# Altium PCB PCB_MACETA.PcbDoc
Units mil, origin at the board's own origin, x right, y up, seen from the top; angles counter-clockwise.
Board outline 2644 x 1425 mil, 2 copper layers (Top Layer, Bottom Layer); 33 components, 22 nets, 122 pads, 124 vias.
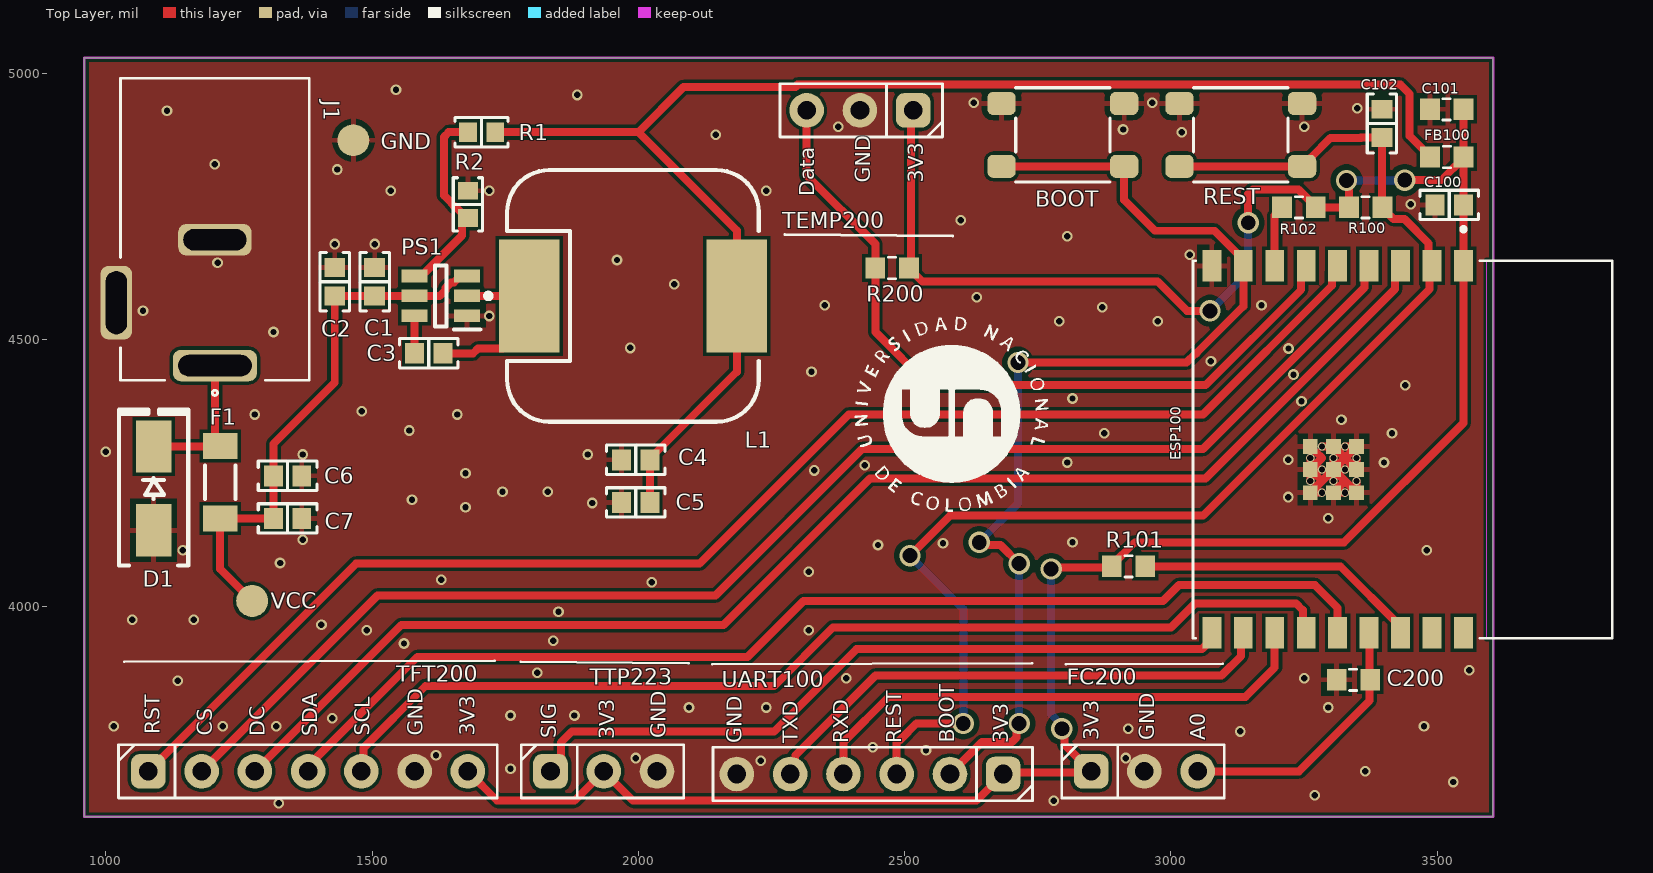
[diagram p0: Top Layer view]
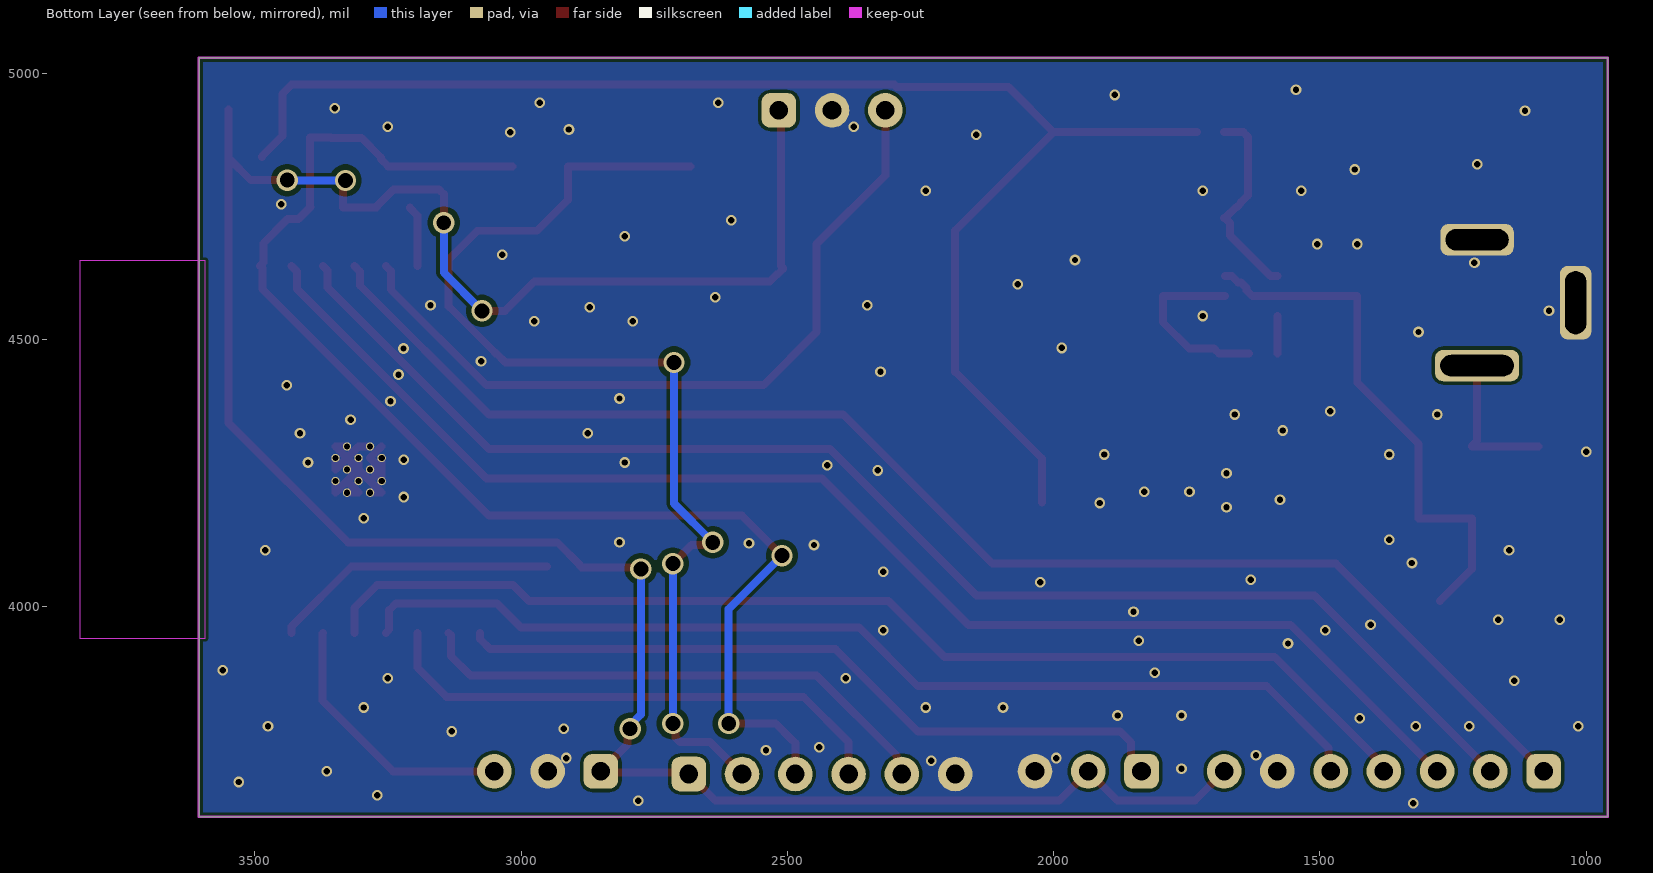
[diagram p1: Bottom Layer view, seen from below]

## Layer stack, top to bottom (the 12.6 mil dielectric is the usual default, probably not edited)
Top Solder: solder mask 0.4, Solder Resist, Dk 3.5
Top Layer: signal copper 1.4
Dielectric 1: dielectric 12.6, FR-4, Dk 4.8
Bottom Layer: signal copper 1.4
Bottom Solder: solder mask 0.4, Solder Resist, Dk 3.5

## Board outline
960,3605 3604,3605 3604,5030 960,5030

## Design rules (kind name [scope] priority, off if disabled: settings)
Clearance Clearance_Vias [IsVia] p1: gap=10 ignorepadtopadclearanceinfootprint=FALSE except(0: Arc-Hole Track-Hole SMDPad-Hole THPad-Hole Via-Hole Fill-Hole Poly-Hole Region-Hole Text-Hole)
Clearance [All] p2: gap=6 ignorepadtopadclearanceinfootprint=FALSE
HoleSize [All] p1: absolutevalues=TRUE maxlimit=200 minlimit=12 maxpercent=80.000 minpercent=20.000
MinimumAnnularRing [All] p1: minimumring=3
MinimumSolderMaskSliver [All] p1: minsoldermaskwidth=4
PolygonConnect PolygonConnect_3 [All vs IsNamedPolygon('GND_Top')] p1: thpad.connectstyle=Direct thpad.reliefconductorwidth=10 thpad.reliefentries=4 thpad.polygonreliefangle="90 Angle" thpad.airgapwidth=10 smdpad.connectstyle=Relief smdpad.reliefconductorwidth=10 smdpad.reliefentries=4 smdpad.polygonreliefangle="90 Angle" smdpad.airgapwidth=10 via.connectstyle=Direct via.reliefconductorwidth=10 via.reliefentries=4 via.polygonreliefangle="90 Angle" via.airgapwidth=10
PolygonConnect PolygonConnect_2 [All vs IsNamedPolygon('GND')] p2: connectstyle=Direct reliefconductorwidth=10 reliefentries=4 polygonreliefangle="90 Angle" airgapwidth=10
PolygonConnect GND [All vs IsNamedPolygon('GND_Top')] p3: thpad.connectstyle=Direct thpad.reliefconductorwidth=10 thpad.reliefentries=4 thpad.polygonreliefangle="90 Angle" thpad.airgapwidth=10 smdpad.connectstyle=Relief smdpad.reliefconductorwidth=10 smdpad.reliefentries=4 smdpad.polygonreliefangle="90 Angle" smdpad.airgapwidth=10 via.connectstyle=Direct via.reliefconductorwidth=10 via.reliefentries=4 via.polygonreliefangle="90 Angle" via.airgapwidth=10
PolygonConnect PolygonConnect_1 [All vs IsNamedPolygon('GND_Top')] p4: thpad.connectstyle=Direct thpad.reliefconductorwidth=10 thpad.reliefentries=4 thpad.polygonreliefangle="90 Angle" thpad.airgapwidth=10 smdpad.connectstyle=Relief smdpad.reliefconductorwidth=10 smdpad.reliefentries=4 smdpad.polygonreliefangle="90 Angle" smdpad.airgapwidth=10 via.connectstyle=Relief via.reliefconductorwidth=10 via.reliefentries=4 via.polygonreliefangle="90 Angle" via.airgapwidth=10
PolygonConnect [All] p5: connectstyle=Direct reliefconductorwidth=8 reliefentries=4 polygonreliefangle="90 Angle" airgapwidth=6
RoomDefinition ESP32 [InComponentClass('ESP32')] p1: confinementstyle=ConfineIn formatcopy=TRUE lockcomponents=FALSE outline 0,0 2000,0 2000,1000 0,1000
RoomDefinition Designator [InComponentClass('Designator')] p2: confinementstyle=ConfineIn formatcopy=TRUE lockcomponents=FALSE outline 0,0 2000,0 2000,1000 0,1000
RoutingVias [All] p1: holewidth=12 width=22 viastyle="Through Hole" minholewidth=12 minwidth=18 maxholewidth=30 maxwidth=40
SilkToSilkClearance [All] p1: silktosilkclearance=2
SilkToSolderMaskClearance [IsPad] p1: minsilkscreentomaskgap=0.1 clearancetoexposedcopper=TRUE
SolderMaskExpansion SolderMaskExpansion_Vias [IsVia] p1: expansion=2 istentingtop=TRUE
SolderMaskExpansion [All] p2: expansion=2 istentingtop=FALSE
Width [All] p1: maxlimit=100 minlimit=6 preferedwidth=10
26 further rules are at their usual default settings.

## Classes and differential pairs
component class POWER: C1 C2 C3 C4 C5 D1 F1 J1 L1 PS1 R1 R2 VCC vcc
component class ESP32: BOOT C100 C101 C102 ESP100 FB100 R100 R101 R102 REST UART100
component class Designator: C200 FC200 R200 TEMP200 TFT200 TTP223

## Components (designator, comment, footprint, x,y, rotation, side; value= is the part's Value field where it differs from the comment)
BOOT "Sw" Sw_PUSH_4.5x4.5x5mm 2797,4885 r180 top (schematic designator SW100)
C1 "4.7 µF" "CAP 0603_1608" 1505,4609.17 r270 top
C2 "0.1 µF" "CAP 0603_1608" 1430,4609.17 r270 top
C3 "0.1 µF" "CAP 0603_1608" 1606.57,4475 r180 top
C4 "22 µF" "CAP 0603_1608" 1995,4275 r0 top
C5 "22 µF" "CAP 0603_1608" 1995,4195 r0 top
C6 "0.1 µF" "CAP 0603_1608" 1341.57,4245 r180 top
C7 "10 µF" "CAP 0603_1608" 1341.57,4165 r180 top
C100 "10 µF" "CAP 0603_1608" 3522.52,4753.39 r0 top
C101 "0.1uF 50V" 0603_cap#1 3517.59,4933 r180 top value=0.1uF
C102 "1 µF" "CAP 0603_1608" 3396,4906.43 r270 top
C200 "0.1uF 50V" 0603_cap#2 3342.5,3862 r180 top value=0.1uF
D1 "SMAJ5.0A" "DO214AC SMA" 1090,4221.26 r90 top
ESP100 "ESP32-C3-WROOM-02-N4" ESP32-C3-WROOM-02-N4 3312.87,4294.49 r270 top
F1 "MFU1206FF05000P100" "FUSE 1206_3216 0.6MM" 1215,4232.91 r270 top
FB100 "60OHM 2A" 0603_fb 3517.59,4843.35 r0 top value="60 OHM"
FC200 "3x1" H_3X1_TH_100mil 2950,3690 r0 top
GND "GND" Pad_SMD 1465,4875 r90 top (schematic designator TP2)
J1 "PWR JACK 2.1mm" CON_POWER_BARREL_2.1MM_3CONN 1205,4570 r180 top
L1 "5.6 µH" "WURTH WE-PD 1280" 1989.88,4582.6 r0 top (schematic designator L?)
PS1 "LMR51430XDDCR" SOT95P280X110-6N 1629.21,4582.6 r180 top
R1 "100 kOhms" "RES 0603_1608" 1705.59,4890 r0 top
R2 "22.1 kOhms" "RES 0603_1608" 1680,4754.41 r270 top
R100 "10k 1/10W" 0603_res 3365.5,4749 r180 top value=10k
R101 "10k 1/10W" 0603_res 2920,4075 r0 top value=10k
R102 "10k 1/10W" 0603_res 3240,4749 r0 top value=10k
R200 "4k7 1/10W" 0603_res 2476.5,4635 r180 top value=4k7
REST "Sw" Sw_PUSH_4.5x4.5x5mm 3131,4885 r180 top (schematic designator SW101)
TEMP200 "3x1" H_3X1_TH_100mil 2416,4931 r180 top
TFT200 "7x1" H_7x1_TH_100mil 1380,3690 r0 top
TTP223 "3x1" H_3X1_TH_100mil 1935,3690 r0 top
UART100 "6x1" H_6x1_TH_100mil 2435,3685 r180 top
VCC "5V" Pad_SMD 1275,4010 r0 top (schematic designator TP1)

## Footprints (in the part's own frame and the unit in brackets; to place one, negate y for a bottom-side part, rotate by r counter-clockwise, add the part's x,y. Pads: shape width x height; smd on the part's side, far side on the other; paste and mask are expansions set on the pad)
0603_cap#1 [mil]
  rect 37x40 smd: 2(-31.5,0) 2(31.5,0)
  silkscreen extent -7,-20 8,20, body extent -31,-17 31,17, height 34
0603_cap#2 [mil]
  rect 37x40 smd: 1(-31.5,0) 2(31.5,0)
  silkscreen extent -7,-20 8,20, body extent -31,-17 31,17, height 34
0603_fb [mil]
  rect 37x40 smd: 1(-31.5,0) 2(31.5,0)
  silkscreen extent -6,-20 8,20, body extent -32,-16 31,16, height 32
0603_res [mil] "1608 Metric / 20190225 / C-A.Serna.A"
  rect 37x40 smd: 1(-31.5,0) 2(31.5,0)
  silkscreen extent -7,-20 8,20, body extent -31,-16 32,16, height 12
"CAP 0603_1608" [mm] "Chip Capacitor, 2-Leads, Body 1.60x0.80mm, IPC Medium Density"
  rect 0.9x1 smd: 1(-0.675,0) 2(0.675,0)
  silkscreen extent -1.4,-0.7 1.4,0.7, body extent -0.8,-0.41 0.8,0.41, height 0.82
CON_POWER_BARREL_2.1MM_3CONN [mm]
  rrect50% 4x1.5 hole 1.016 slot 3.5 at 0 deg: 1(0,3)
  rrect50% 3.5x1.5 hole 1.016 slot 3 at 0 deg: 2(0,-3)
  rrect50% 1.5x3.5 hole 1.016 slot 3 at 90 deg: 3(4.7,0)
  silkscreen extent -4.5,-10.7 4.5,4.42, body extent -4.5,-10.7 4.9,3.7, height 11
"DO214AC SMA" [mm] "Molded Diode, 2-Leads, Body 4.30x2.60mm, IPC Medium Density"
  rect 2.5x1.7 smd: 1(-2,0) 2(2,0)
  silkscreen extent -3.68,-1.65 3.75,1.65, body extent -2.6,-1.37 2.6,1.37, height 2.4
ESP32-C3-WROOM-02-N4 [mm]
  rect 1.5x0.9 smd: 1(-8.75,6) 2(-8.75,4.5) 3(-8.75,3) 4(-8.75,1.5) 5(-8.75,0) 6(-8.75,-1.5) 7(-8.75,-3) 8(-8.75,-4.5) 9(-8.75,-6) 10(8.75,-6) 11(8.75,-4.5) 12(8.75,-3) 13(8.75,-1.5) 14(8.75,0) 15(8.75,1.5) 16(8.75,3) 17(8.75,4.5) 18(8.75,6)
  rect 0.7x0.7 smd: 19(-0.14,0.9) 19(-0.14,-0.2) 19(-0.14,-1.3) 19(0.96,0.9) 19(0.96,-0.2) 19(0.96,-1.3) 19(2.06,-0.2) 19(2.06,0.9) 19(2.06,-1.3)
  round 0.4 hole 0.3 mask+0: 19(-0.14,0.35) 19(-0.14,-0.75) 19(0.41,0.9) 19(0.41,-0.2) 19(0.41,-1.3) 19(0.96,0.35) 19(0.96,-0.75) 19(1.51,0.9) 19(1.51,-0.2) 19(1.51,-1.3) 19(2.06,-0.75) 19(2.06,0.35)
  Keep-Out Layer region: 9,7.1 -9,7.1 -9,13.1 9,13.1
  Keep-Out Layer region: 9,7.1 -9,7.1 -9,13.1 9,13.1
  silkscreen extent -10.6,-6.9 9,13.1, body extent -9,-6.9 9,13.1, height 3.35
"FUSE 1206_3216 0.6MM" [mm] "Chip Fuse 1.5A AC 63V DC, 2-Leads, Body 3.10x1.55mm, IPC Medium Densitym"
  rect 1.25x1.65 smd: 1(-1.725,0) 2(1.725,0)
  silkscreen extent -0.8,-0.72 0.8,0.72, body extent -1.55,-0.77 1.55,0.78, height 0.76
H_3X1_TH_100mil [mil]
  rrect50% 65x65 hole 35: 1(-100,0)
  round 65 hole 35: 2(0,0) 3(100,0)
  silkscreen extent -155,-50 150,50, body extent -142,-46 142,46, height 320
H_6x1_TH_100mil [mil]
  rrect50% 65x65 hole 35: 1(-250,0)
  round 65 hole 35: 2(-150,0) 3(-50,0) 4(50,0) 5(150,0) 6(250,0)
  silkscreen extent -305,-50 295,50
H_7x1_TH_100mil [mil]
  rrect50% 65x65 hole 35: 1(-300,0)
  round 65 hole 35: 2(-200,0) 3(-100,0) 4(0,0) 5(100,0) 6(200,0) 7(300,0)
  silkscreen extent -356,-50 355,50
Pad_SMD [mil]
  round 60 smd: 2(0,0)
"RES 0603_1608" [mm] "Chip Resistor, 2-Leads, Body 1.60x0.80mm, IPC Medium Density"
  rect 0.85x0.95 smd: 1(-0.65,0) 2(0.65,0)
  silkscreen extent -1.27,-0.7 1.27,0.7, body extent -0.8,-0.4 0.8,0.4, height 0.45
SOT95P280X110-6N [mm]
  rect 1.25x0.6 smd: 1(-1.25,0.95) 2(-1.25,0) 3(-1.25,-0.95) 4(1.25,-0.95) 5(1.25,0) 6(1.25,0.95)
  silkscreen extent -1.88,-1.45 0.28,1.6, body extent -1.4,-1.45 1.4,1.45, height 0.97
Sw_PUSH_4.5x4.5x5mm [mm]
  rrect50% 1.35x1.1 smd: 1(-2.925,1.5) 1(2.925,1.5) 2(-2.925,-1.5) 2(2.925,-1.5)
  silkscreen extent -2.25,-2.25 2.25,2.25, body extent -2.25,-2.25 2.25,2.25, height 5
"WURTH WE-PD 1280" [mm] "SMT Shielded Power Inductor, 2-leads, body 12x12mm"
  rect 2.9x5.4 smd: 1(-4.95,0) 2(4.95,0)
  silkscreen extent -7.02,-6 6,6, body extent -6,-6 6,6, height 7.51

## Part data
BOOT REST: library part Sw_PUSH_4.5x4.5x5.0xmm, "SWITCH TACTILE SPST-NO 0.05A 12V", Manufacturer=BZCN, Manufacturer Part Number=TSC015A05026A, Supplier Part Number 1=C2888509
C1: library part 06033D475KAT2A, "CAP CER 4.7UF 25V X5R 0603", Device Package="0603 (1608 Metric)", Manufacturer="KYOCERA AVX", Operating Temperature="-55°C ~ 85°C", Supplier Part Number 1=478-KGM15CR51E475KTCT-ND, Temperature Coefficient=X5R, Tolerance=±10%, Voltage - Rated=25V
C2 C3 C6: library part CL10E104KC8VPNC, "CAP CER 100NF 100V X8L 0603", Device Package="0603 (1608 Metric)", Manufacturer="Samsung Electro-Mechanics", Operating Temperature="-55°C ~ 150°C", Ratings=AEC-Q200, Supplier Part Number 1=1276-CL10E104KC8VPNCCT-ND, Temperature Coefficient=X8L, Tolerance=±10%, Voltage - Rated=100V
C4 C5: library part 0603YD226MAT2A, "CAP CER 22UF 16V X5R 0603", Device Package="0603 (1608 Metric)", Manufacturer="KYOCERA AVX", Operating Temperature="-55°C ~ 85°C", Supplier Part Number 1=478-KGM15CR51C226MTCT-ND, Temperature Coefficient=X5R, Tolerance=±20%, Voltage - Rated=16V
C7: library part 0603X106M100CT, "CAP CER 10UF 10V X5R 0603", Device Package="0603 (1608 Metric)", Manufacturer="Walsin Technology Corporation", Operating Temperature="-55°C ~ 85°C", Supplier Part Number 1=1292-0603X106M100CT-ND, Temperature Coefficient=X5R, Tolerance=±20%, Voltage - Rated=10V
C100: library part 06033D106KAT2A, "CAP CER 10UF 25V X5R 0603", Device Package="0603 (1608 Metric)", Manufacturer="KYOCERA AVX", Operating Temperature="-55°C ~ 85°C", Supplier Part Number 1=478-KGM15CR51E106KTCT-ND, Temperature Coefficient=X5R, Tolerance=±10%, Voltage - Rated=25V
C101 C200: library part Cap_0.1uF_0603_50V, "50V 100nF Y5V -20%~+80% 0603 Multilayer Ceramic Capacitors MLCC - SMD/SMT ROHS", Manufacturer="Walsin Tech Corp", Manufacturer Part Number=0603F104Z500CT, Supplier Part Number 1=C83060
C102: library part 0603B105K250CT, "CAP CER 1UF 25V X7R 0603", Device Package="0603 (1608 Metric)", Manufacturer="Walsin Technology Corporation", Operating Temperature="-55°C ~ 125°C", Supplier Part Number 1=1292-0603B105K250CT-ND, Temperature Coefficient=X7R, Tolerance=±10%, Voltage - Rated=25V
D1: "TVS DIODE 5VWM 9.2VC DO214AC", Current - Peak Pulse (10/1000µs)=43.5A, Manufacturer="Littelfuse Inc.", Operating Temperature="-65°C ~ 150°C (TJ)", Package / Case="DO-214AC, SMA", Power - Peak Pulse=400W, Power Line Protection=No, Supplier Device Package="DO-214AC (SMA)", Supplier Part Number 1=SMAJ5.0ALFCT-ND, Voltage - Breakdown (Min)=6.4V, Voltage - Clamping (Max) @ Ipp=9.2V, Voltage - Reverse Standoff (Typ)=5V
ESP100: library part MCU_ESP32-C3-WROOM-02-N4, "RF TXRX MOD BT WIFI PCB TH SMD", Manufacturer="Espressif Systems", Supplier Part Number 1=C2934560
F1: "FUSE BOARD MOUNT 5A 63VDC 1206", Breaking Capacity @ Rated Voltage=50A, Current Rating (Amps)=5A, Device Package="1206 (3216 Metric)", Manufacturer="Vishay Beyschlag", Operating Temperature="-55°C ~ 125°C", Supplier Part Number 1=MFU12065.00CT-ND, Voltage Rating - DC=63V
FB100: library part FB_60_0603_2A, "2A 1 100mΩ 60Ω@100MHz ±25% 0603 Ferrite Beads ROHS", Manufacturer=TAI-TECH, Manufacturer Part Number=HCB1608KF-600T20, Supplier Part Number 1=C369516
FC200 TEMP200 TTP223: library part H_Male_3x1_TH_100mil, "H_Male_3x1_TH_100mil"
GND VCC: library part Test, "Test1.5mm"
J1: library part Con_Power_Jack_2.1mm_3pins, "CONN PWR JACK 2X5.5MM SOLDER", Manufacturer=HCTL, Manufacturer Part Number=HC-DC-005-2.0T, Supplier Part Number 1=C3010533
L1: library part 74477005, "FIXED IND 5.6UH 8A 17 MOHM SMD", Current - Saturation=8.2A, Current Rating (Amps)="8 A", DC Resistance (DCR)="17mOhm Max", Device Package=Nonstandard, Frequency - Self Resonant=24MHz, Inductance Frequency - Test="1 kHz", Manufacturer="Würth Elektronik", Operating Temperature="-40°C ~ 125°C", Ratings=AEC-Q200, Supplier Part Number 1=732-13489-1-ND, Tolerance="-20%, +40%"
PS1: "Power Supply", Manufacturer_Name="Texas Instruments", Mouser Part Number=595-LMR51430XDDCR
R1: library part AA0603FR-07100KL, "RES SMD 100K OHM 1% 1/10W 0603", Device Package="0603 (1608 Metric)", Manufacturer=Yageo, Operating Temperature="-55°C ~ 155°C", Power (Watts)="0.1W, 1/10W", Ratings=AEC-Q200, Supplier Device Package=0603, Supplier Part Number 1=13-AA0603FR-07100KLCT-ND, Temperature Coefficient=±150ppm/°C, Tolerance=±1%
R2: library part AC0603FR-0722K1L, "RES SMD 22.1K OHM 1% 1/10W 0603", Device Package="0603 (1608 Metric)", Manufacturer=Yageo, Operating Temperature="-55°C ~ 155°C", Power (Watts)="0.1W, 1/10W", Ratings=AEC-Q200, Supplier Device Package=0603, Supplier Part Number 1=YAG5325CT-ND, Temperature Coefficient=±100ppm/°C, Tolerance=±1%
R100 R101 R102: library part Res_10k_0603_1/10W, "RES SMD 10k OHM 5% 1/10W 0603", Manufacturer=FOJAN, Manufacturer Part Number=FRC0603J103TS, Supplier Part Number 1=C2930027
R200: library part Res_4k7_0603_1/10W, "100mW Thick Film Resistor 75V ±1% 4.7kΩ 0603 Chip Resistor - Surface Mount ROHS", Manufacturer=VO, Manufacturer Part Number=SCR0603F4K7, Supplier Part Number 1=C3016318
TFT200: library part H_Male_7x1_TH_100mil, "H_Male_7x1_TH_100mil"
UART100: library part H_Male_6x1_TH_100mil, "H_Male_6x1_TH_100mil"

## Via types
v1: diameter 20, hole 12, Top Layer to Bottom Layer, tented both sides, 112 vias
v2: diameter 40, hole 28, Top Layer to Bottom Layer, tented both sides, 12 vias

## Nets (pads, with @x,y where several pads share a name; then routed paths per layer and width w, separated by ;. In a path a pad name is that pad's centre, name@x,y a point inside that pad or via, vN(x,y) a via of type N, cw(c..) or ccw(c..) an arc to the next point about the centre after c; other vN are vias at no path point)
3.3V: C4.2 C5.2 FB100.1 L1.2 R1.2 | length 2734.5
  Top Layer w15: R1.2 2000,4890 ; C5.2 C4.2 2021.57,4276.97 2184.76,4440.16 L1.2 2184.76,4705.24 2000,4890 ; FB100.1 3486.09,4844.85 3448.19,4882.76 3448.19,4961.81 3430.79,4979.21 2299.16,4979.21 2294.95,4975 2085,4975 2000,4890
5V: C1.2 C2.2 C6.2 C7.2 F1.2 PS1.3 PS1.5 VCC.2 | length 1011.5
  Top Layer w15: VCC.2 1215,4070 F1.2 C7.2 C6.2 1315,4305 1430,4420 C2.2 C1.2 PS1.5 1627.11,4582.6 1637.67,4593.16 1637.67,4597.35 1648.23,4607.91 1653.54,4607.91 1665.63,4620 PS1.3
A0: C200.1 ESP100.15 FC200.3 | length 505.5
  Top Layer w15: FC200.3 3240,3690 3372.96,3822.96 3372.96,3948.96 ESP100.15
BOOT: BOOT.1 ESP100.8 UART100.2 | length 2059
  Top Layer w15: UART100.2 2645,3745 2701.43,3745 2710.22,3753.79 2710.22,3775.22 v2(2715,3780) ; v2(2640,4120) 2644.78,4115.22 2679.78,4115.22 v2(2715,4080) ; BOOT.1@2681.84,4825.94 2912.16,4825.94 2912.16,4762.84 2970,4705 3081.5,4705 3135.71,4650.79 3135.71,4563.21 3047.5,4475 3046.46,4475 3029.2,4457.73 v2(2712.68,4457.73)
  Bottom Layer w15: v2(2640,4120) 2712.68,4192.68 v2(2712.68,4457.73) ; v2(2715,3780) v2(2715,4080)
CS: ESP100.4 TFT200.2 | length 2603.8
  Top Layer w15: TFT200.2 1510,4020 2145,4020 2420,4295 3060,4295 3363.42,4598.42 3363.42,4630.47 ESP100.4
DC: ESP100.3 TFT200.3 | length 2563.4
  Top Layer w15: TFT200.3 1555,3965 2160,3965 2435,4240 3065,4240 3420.77,4595.77 3420.77,4628.76 ESP100.3
ESP_EN: C102.2 ESP100.2 R100.1 REST.1 UART100.3 | length 2481
  Top Layer w15: UART100.3 2485,3743.22 2493.79,3752.01 2521.78,3780 v2(2610,3780) ; v2(2510,4095) 2585,4170 3060,4170 3485.74,4595.74 3485.74,4634.67 ESP100.2 3483.5,4645.52 3483.5,4681.5 3438.21,4726.79 3417.71,4726.79 3397,4747.5 R100.1 3396,4749 3395,4750 3396.5,4751.5 3396.5,4879.35 C102.2 3357.03,4879.85 3356.66,4879.48 3299.7,4879.48 3263.18,4842.97 3263.18,4839.85 3249.28,4825.94 3246.16,4825.94 REST.1@3015.84,4825.94
  Bottom Layer w15: v2(2510,4095) 2610,3995 v2(2610,3780)
GND: BOOT.2 C1.1 C2.1 C4.1 C5.1 C6.1 C7.1 C100.1 C101.2@3486.09,4933 C102.1 C200.2 D1.1 ESP100.9 ESP100.19 FC200.2 GND.2 J1.2 J1.3 PS1.1 R2.1 REST.2 TEMP200.2 TFT200.6 TTP223.3 UART100.6 | length 627.3
  Top Layer w15: ESP100.19@3261.69,4235.04 ESP100.19@3261.69,4256.69 ; ESP100.19@3261.69,4278.35 ESP100.19@3261.69,4256.69 ; ESP100.19@3261.69,4300 3272.52,4289.17 3283.35,4278.35 ESP100.19@3261.69,4256.69 ; ESP100.19@3283.35,4213.39 3261.69,4213.39 3283.35,4235.04 ; ESP100.19@3283.35,4256.69 ESP100.19@3261.69,4256.69 ; ESP100.19@3283.35,4300 3305,4300 3326.65,4278.35 ; ESP100.19@3305,4235.04 ESP100.19@3305,4256.69 ; ESP100.19@3305,4278.35 ESP100.19@3305,4256.69 ; ESP100.19@3326.65,4213.39 3305,4213.39 3326.65,4235.04 ; ESP100.19@3326.65,4256.69 ESP100.19@3305,4256.69 ; ESP100.19@3326.65,4300 3348.31,4300 3342.03,4293.72 3326.65,4278.35 ; ESP100.19@3348.31,4235.04 3348.31,4213.39 3342.03,4219.67 3326.65,4235.04 ; ESP100.19@3348.31,4278.35 3348.31,4256.69 3326.65,4278.35 ; ESP100.19@3261.69,4256.69 3272.52,4245.87 3283.35,4235.04 ; 3283.35,4235.04 3298.72,4250.41 ESP100.19@3305,4256.69 ; ESP100.19@3305,4256.69 3326.65,4278.35 ; ESP100.19@3305,4256.69 3326.65,4235.04
  other v1: 1325,3630 2780,3635 3270,3645 3530,3670 3365,3690 1760,3695 2230,3710 1995,3715 2915,3715 1620,3720 2540,3730 2440,3735 3130,3765 2920,3770 1015,3775 1220,3775 1320,3775 3475,3775 1425,3790 1760,3795 1880,3795 2095,3810 2240,3810 3295,3810 1135,3860 2390,3865 3250,3865 1810,3875 3560,3880 1560,3930 1840,3935 1490,3955 2320,3955 1405,3965 1050,3975 1165,3975 1850,3990 2025,4045 1630,4050 2320,4065 1327.35,4081.15 1145,4105 3480,4105 2450,4115 2571.95,4118.05 2815,4120 1370,4125 3295,4165 1675.54,4186.07 1913.18,4193.92 1575,4200 3220,4205 1745,4215 1830,4215 1675.54,4249.7 2330,4255 2425,4265 2805,4270 3400,4270 3220,4275 1370,4285 1905,4285 1000,4290 2875,4325 3415,4325 1570,4330 3320,4350 1280,4360 1660,4360 1480.9,4366.09 3245,4385 2815,4390 3440,4415 3230,4435 2325,4440 3075,4460 3220.64,4484.03 1985,4485 1315,4515 2790,4535 2975,4535 1720,4545 1070,4555 2870.91,4561.4 2350,4565 3170,4565 2635,4580 2067.67,4604.77 1210,4645 1960,4650 3035,4660 1430,4680 1505,4680 2805,4695 2605,4725 3450,4755 1535,4780 1720,4780 2240,4780 1435,4820 1205,4830 2145,4885 3020,4890 2910,4895 2375,4900 3250,4900 1115,4930 3350,4935 2630,4945 2965,4945 1885,4960 1545,4970
NetC3_1: C3.1 L1.1 PS1.2 | length 351.8
  Top Layer w15: C3.1 1689.99,4475 1698.79,4483.8 1745.41,4483.8 1795,4533.39 L1.1 PS1.2
NetC3_2: C3.2 PS1.6 | length 70.2
  Top Layer w15: C3.2 PS1.6
NetD1_2: D1.2 F1.1 J1.1 | length 280.5
  Top Layer w15: D1.2 1214.17,4300 F1.1 1205,4310.83 J1.1
NetESP100_7: ESP100.7 R102.1 | length 115.7
  Top Layer w15: ESP100.7 3194.76,4733.76 3208.5,4747.5 R102.1
NetESP100_16: ESP100.16 R101.2 | length 538.2
  Top Layer w15: R101.2 3317.8,4075 3430.98,3961.81 ESP100.16
NetPS1_4: PS1.4 R1.1 R2.2 | length 378.2
  Top Layer w15: PS1.4 1592.8,4620 1668.8,4696 1668.8,4719.59 R2.2@1678.03,4728.82 ; R2.2 R2.2@1678.03,4728.82 ; R1.1 1644.01,4890 1635.23,4881.21 1635.23,4771.62 1647.8,4759.05 1647.8,4757.68 1655.71,4749.77 1657.08,4749.77 R2.2@1678.03,4728.82
RST: ESP100.5 TFT200.1 | length 2641.2
  Top Layer w15: TFT200.1 1470,4080 2115,4080 2395,4360 3060,4360 3302.66,4602.66 3302.66,4628.76 ESP100.5
RXD: ESP100.11 UART100.5 | length 998.1
  Top Layer w15: UART100.5 2294.57,3694.57 2294.57,3719.57 2445,3870 3095,3870 3131.76,3906.76 3131.76,3946.05 ESP100.11
SCL: ESP100.13 TFT200.5 | length 1971.7
  Top Layer w15: TFT200.5 1483.89,3693.89 1483.89,3733.89 1600,3850 2255,3850 2365,3960 3000,3960 3045,4005 3235,4005 3247.38,3992.62 3247.38,3956.44 ESP100.13
SDA: ESP100.14 TFT200.4 | length 2148.6
  Top Layer w15: TFT200.4 1380,3700 1585,3905 2205,3905 2310,4010 2985,4010 3015,4040 3270,4040 3312.87,3997.13 ESP100.14
SIG: ESP100.10 TTP223.1 | length 1376.8
  Top Layer w15: TTP223.1 1854.6,3709.6 1854.6,3744.6 1875,3765 2255,3765 2410,3920 3058.46,3920 3076.65,3938.19 ESP100.10
TEMP_DATA: ESP100.6 R200.2 TEMP200.3 | length 1433
  Top Layer w15: TEMP200.3 2316,4809 2445,4680 R200.2 2445,4595 2445.1,4594.9 2445.1,4514.9 2545,4415 3065,4415 3244.37,4594.37 3244.37,4629.52 ESP100.6
TXD: ESP100.12 UART100.4 | length 992.9
  Top Layer w15: UART100.4 2385,3745 2470,3830 3140,3830 3194.76,3884.76 ESP100.12
V_ESP: C100.2 C101.2@3549.09,4933 ESP100.1 FB100.2 FC200.1 R100.2 R101.1 R102.2 R200.1 TEMP200.1 TFT200.7 TTP223.2 UART100.1 | length 4794
  Top Layer w15: TFT200.7 1735,3635 1880,3635 TTP223.2 ; TTP223.2@1934.43,3689.09 1935.91,3689.09 1990,3635 2635,3635 UART100.1 2687.5,3687.5 2847.5,3687.5 FC200.1 2799.78,3740.22 2799.78,3765.22 v2(2795,3770) ; TEMP200.1 2512,4927 2512,4639 R200.1 2508,4633.5 2519,4622.5 2520.5,4622.5 2533,4610 2975,4610 3030.45,4554.55 v2(3073.1,4554.55) ; v2(2775,4070) 2777.5,4072.5 2886,4072.5 R101.1 2888.5,4076.5 2932,4120 3325,4120 3549.09,4344.09 ESP100.1 C100.2 FB100.2@3549.09,4841.85 ; v2(3145,4720) 3145,4773.71 3153.79,4782.5 3239.5,4782.5 3271.5,4750.5 R102.2 R100.2 3334,4795.03 v2(3329.62,4799.41) ; v2(3438.86,4799.98) 3507.23,4799.98 FB100.2@3549.09,4841.85 ; C101.2@3549.09,4933 FB100.2 FB100.2@3549.09,4841.85
  Bottom Layer w15: v2(2775,4070) 2775,3796.76 2795,3776.76 v2(2795,3770) ; v2(3073.1,4554.55) 3145,4626.45 v2(3145,4720) ; v2(3329.62,4799.41) 3438.29,4799.41 v2(3438.86,4799.98)
pads on no net: ESP100.17 ESP100.18

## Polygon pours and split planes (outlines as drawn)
GND on Top Layer "GND_Top" (solid, remove dead copper, pour order 0): 960,3605 3605,3605 3604,5030 960,5030
GND on Bottom Layer "GND_BOOT" (solid, remove dead copper, pour order 4): 960,3605 3604,3605 3604,5030 960,5030

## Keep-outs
Keep-Out Layer:
  lines w5: 960,3605 960,5030 3605,5030 3605,3605 960,3605

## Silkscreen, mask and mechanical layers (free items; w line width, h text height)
Top Overlay:
  drawing of 35 lines, arcs and shapes, not listed
  text "GND" at 2435,4795 h28 r90
  text "3V3" at 2535,4795 h28 r90
  text "Data" at 2330,4770 h28 r90
  text "RST" at 1101,3760 h28 r90
  text "CS" at 1200,3757 h28 r90
  text "SCL" at 1496,3757 h28 r90
  text "GND" at 1595,3757 h28 r90
  text "3V3" at 1693,3757 h28 r90
  text "DC" at 1299,3756 h28 r90
  text "SDA" at 1397.5,3756 h28 r90
  text "SIG" at 1846,3752 h28 r90
  text "GND" at 2051,3752 h28 r90
  text "3V3" at 1955,3750 h28 r90
  text "3V3" at 2864,3748 h28 r90
  text "GND" at 2969,3748 h28 r90
  text "A0" at 3064,3748 h28 r90
  text "BOOT" at 2593,3744 h28 r90
  text "GND" at 2194,3743 h28 r90
  text "TXD" at 2299,3743 h28 r90
  text "RXD" at 2394,3743 h28 r90
  text "REST" at 2494,3743 h28 r90
  text "3V3" at 2694,3743 h28 r90
BOARD_SHAPE:
  lines w5: 960,3605 3605,3605 3605,5030 960,5030 960,3605

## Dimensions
960,5030 to 960,3605 on BOARD_SHAPE
960,3605 to 3605,3620 on BOARD_SHAPE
